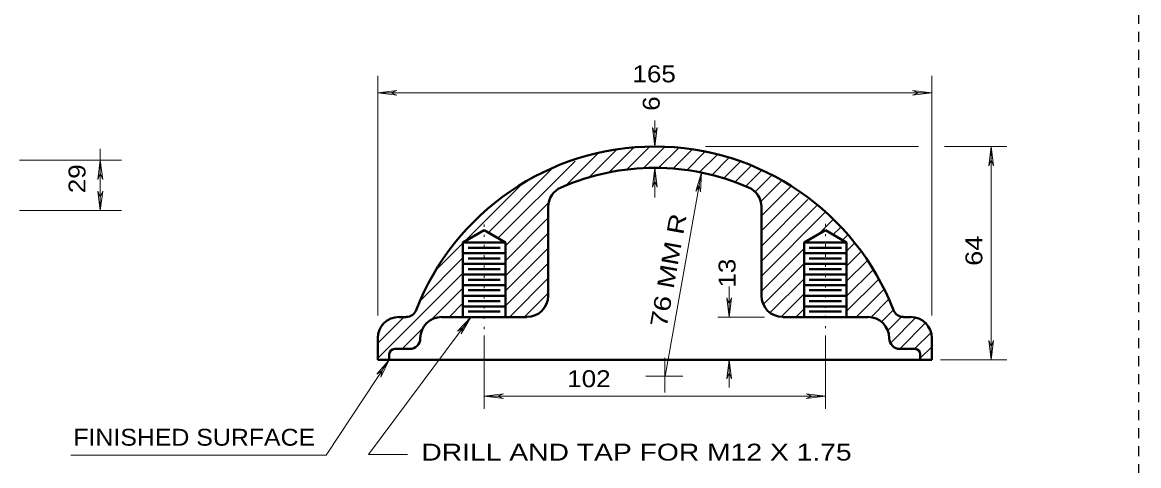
# Model space of a CAD drawing. Extents: x 312583 to 312853, y 144419 to 144586.
# Drawn here: x 312718.5 to 312768.6, y 144534.6 to 144554.6 of the extents above; entities that cross this region are included whole.
import ezdxf

# ---------------------------------------------------------------- set-up
doc = ezdxf.new("R2010")
doc.units = 0
doc.header["$LTSCALE"] = 0.3
doc.linetypes.add('DOTTED', pattern=[1.5, 0.3, -1.2])
doc.linetypes.add('SHORT_DASHED', pattern=[2.7, 1.5, -1.2])
doc.layers.add('1', color=7, linetype='Continuous', lineweight=13)

msp = doc.modelspace()

# ---------------------------------------------------------------- linework, layer by layer
at = {"layer": '1', "linetype": 'SHORT_DASHED', "lineweight": 25}
msp.add_line((312768.638, 144508.3213), (312768.638, 144560.0713), dxfattribs=at)
at = {"layer": '1'}
for p, q in [((312734.4268, 144541.3737), (312734.4268, 144552.1607)), ((312759.3435, 144541.3737), (312759.3435, 144552.1607)), ((312734.4268, 144551.3941), (312735.2931, 144551.5014)), ((312735.2931, 144551.5014), (312735.0171, 144551.3941)), ((312758.4771, 144551.5014), (312758.7531, 144551.3941)), ((312759.3435, 144551.3941), (312758.4771, 144551.5014)), ((312734.4268, 144551.3941), (312759.3435, 144551.3941)), ((312734.4268, 144551.3941), (312735.2931, 144551.2867)), ((312735.2931, 144551.2867), (312735.0171, 144551.3941)), ((312758.4771, 144551.2867), (312758.7531, 144551.3941)), ((312759.3435, 144551.3941), (312758.4771, 144551.2867)), ((312746.8851, 144548.9714), (312746.8851, 144550.1444)), ((312746.7778, 144549.8377), (312746.8851, 144549.5617)), ((312746.8851, 144548.9714), (312746.7778, 144549.8377)), ((312746.9925, 144549.8377), (312746.8851, 144549.5617)), ((312746.8851, 144548.9714), (312746.9925, 144549.8377)), ((312745.6278, 144547.9364), (312746.6475, 144548.9637)), ((312749.1698, 144548.9714), (312758.7455, 144548.9714)), ((312759.9031, 144548.9714), (312762.7168, 144548.9714)), ((312762.0115, 144548.9714), (312761.9041, 144548.1051)), ((312762.0115, 144539.3881), (312762.0115, 144548.9714)), ((312762.0115, 144548.9714), (312762.1188, 144548.1051)), ((312721.9556, 144546.1026), (312721.9556, 144548.8703)), ((312742.8525, 144547.2004), (312744.3168, 144548.6647)), ((312743.8798, 144547.5454), (312745.1755, 144548.8411)), ((312744.8228, 144547.8137), (312745.9115, 144548.9024)), ((312746.3715, 144548.0054), (312747.3068, 144548.9407)), ((312747.0538, 144548.0131), (312747.9278, 144548.8871)), ((312747.7055, 144547.9824), (312748.5565, 144548.8334)), ((312748.3188, 144547.9211), (312749.1315, 144548.7337)), ((312748.8938, 144547.8214), (312749.6681, 144548.5957)), ((312718.3216, 144548.3643), (312722.9063, 144548.3643)), ((312721.9556, 144548.3643), (312721.8483, 144547.4979)), ((312721.9556, 144548.3643), (312722.063, 144547.4979)), ((312739.4025, 144545.1074), (312742.2775, 144547.9824)), ((312739.8395, 144544.8621), (312743.2971, 144548.3197)), ((312746.8851, 144548.0131), (312746.7778, 144547.1467)), ((312746.8851, 144546.6791), (312746.8851, 144548.0131)), ((312746.8851, 144548.0131), (312746.9925, 144547.1467)), ((312749.4458, 144547.6911), (312750.2048, 144548.4501)), ((312749.9595, 144547.5301), (312750.7338, 144548.3044)), ((312750.4655, 144547.3537), (312751.2168, 144548.1127)), ((312761.9041, 144548.1051), (312762.0115, 144548.3811)), ((312762.1188, 144548.1051), (312762.0115, 144548.3811)), ((312721.8483, 144547.4979), (312721.9556, 144547.7739)), ((312722.063, 144547.4979), (312721.9556, 144547.7739)), ((312747.3451, 144538.6444), (312748.9781, 144547.8061)), ((312748.9781, 144547.8061), (312748.7251, 144546.9704)), ((312748.9781, 144547.8061), (312748.9321, 144546.9321)), ((312750.9638, 144547.1774), (312751.6691, 144547.8827)), ((312751.3778, 144546.9167), (312752.1138, 144547.6527)), ((312721.8483, 144546.9689), (312721.9556, 144546.6929)), ((312721.9556, 144546.1026), (312721.8483, 144546.9689)), ((312722.063, 144546.9689), (312721.9556, 144546.6929)), ((312721.9556, 144546.1026), (312722.063, 144546.9689)), ((312738.3138, 144544.6934), (312740.9205, 144547.3001)), ((312746.7778, 144547.1467), (312746.8851, 144547.4227)), ((312746.9925, 144547.1467), (312746.8851, 144547.4227)), ((312748.7251, 144546.9704), (312748.8785, 144547.2234)), ((312748.9321, 144546.9321), (312748.8785, 144547.2234)), ((312751.6461, 144546.5027), (312752.5661, 144547.4227)), ((312751.6768, 144545.8587), (312752.9878, 144547.1697)), ((312740.1845, 144544.5247), (312742.1778, 144546.5257)), ((312751.6768, 144545.1841), (312753.3788, 144546.8861)), ((312751.6768, 144544.5017), (312753.7698, 144546.5947)), ((312718.3216, 144546.1026), (312722.9063, 144546.1026)), ((312751.6768, 144543.8271), (312754.1685, 144546.3187)), ((312751.6768, 144543.1524), (312754.5595, 144546.0351)), ((312740.1845, 144543.8501), (312742.0935, 144545.7667)), ((312754.2375, 144545.0307), (312754.8891, 144545.6824)), ((312740.1845, 144543.1754), (312742.0935, 144545.0844)), ((312754.8968, 144545.0154), (312755.2111, 144545.3221)), ((312755.3261, 144544.7624), (312755.5255, 144544.9694)), ((312737.0795, 144543.4591), (312738.2678, 144544.6474)), ((312755.5101, 144544.2717), (312755.8475, 144544.6091)), ((312736.3818, 144542.0791), (312738.2601, 144543.9651)), ((312740.1845, 144542.4931), (312742.0935, 144544.4097)), ((312751.6768, 144542.4701), (312753.5935, 144544.3867)), ((312755.5101, 144543.5971), (312756.1695, 144544.2487)), ((312740.1845, 144541.8184), (312742.0935, 144543.7274)), ((312751.7995, 144541.9104), (312753.5935, 144543.7121)), ((312755.5101, 144542.9147), (312756.4301, 144543.8347)), ((312734.4268, 144539.4494), (312738.2601, 144543.2827)), ((312740.3455, 144541.3047), (312742.0935, 144543.0527)), ((312752.0908, 144541.5271), (312753.5935, 144543.0297)), ((312755.5101, 144542.2401), (312756.6908, 144543.4131)), ((312755.5101, 144541.5654), (312756.9438, 144542.9914)), ((312736.8571, 144541.2051), (312738.2601, 144542.6081)), ((312750.2278, 144541.3047), (312750.2278, 144542.6847)), ((312755.9318, 144541.3047), (312757.1891, 144542.5621)), ((312737.6391, 144541.3047), (312738.2601, 144541.9334)), ((312741.0278, 144541.3124), (312742.0935, 144542.3781)), ((312750.1205, 144542.1711), (312750.2278, 144541.8951)), ((312750.2278, 144541.3047), (312750.1205, 144542.1711)), ((312750.3351, 144542.1711), (312750.2278, 144541.8951)), ((312750.2278, 144541.3047), (312750.3351, 144542.1711)), ((312752.5738, 144541.3277), (312753.5935, 144542.3551)), ((312756.5835, 144541.2741), (312757.4115, 144542.1097)), ((312753.2255, 144541.3047), (312753.5935, 144541.6727)), ((312757.0435, 144541.0594), (312757.6108, 144541.6267)), ((312734.0128, 144535.1177), (312738.6205, 144541.3047)), ((312734.4268, 144540.1317), (312735.5845, 144541.2894)), ((312738.6205, 144541.3047), (312738.0148, 144540.6761)), ((312738.6205, 144541.3047), (312738.1835, 144540.5457)), ((312751.8225, 144541.3047), (312749.7141, 144541.3047)), ((312757.3425, 144540.6837), (312757.9865, 144541.3277)), ((312757.5188, 144540.1777), (312758.6075, 144541.2664)), ((312757.8945, 144539.8787), (312759.0751, 144541.0594)), ((312735.5231, 144539.8711), (312736.5351, 144540.8831)), ((312738.0148, 144540.6761), (312738.2678, 144540.8294)), ((312738.1835, 144540.5457), (312738.2678, 144540.8294)), ((312739.2185, 144540.4691), (312739.2185, 144537.1724)), ((312754.5518, 144540.4691), (312754.5518, 144537.1724)), ((312758.5615, 144539.8711), (312759.3128, 144540.6147)), ((312758.8221, 144539.4494), (312759.3435, 144539.9707)), ((312761.9041, 144540.2544), (312762.0115, 144539.9784)), ((312762.0115, 144539.3881), (312761.9041, 144540.2544)), ((312762.1188, 144540.2544), (312762.0115, 144539.9784)), ((312762.0115, 144539.3881), (312762.1188, 144540.2544)), ((312747.3375, 144537.9084), (312747.3375, 144539.4724)), ((312734.9481, 144539.3881), (312732.1109, 144535.0937)), ((312734.9481, 144539.3881), (312734.3808, 144538.7287)), ((312734.9481, 144539.3881), (312734.5648, 144538.6061)), ((312750.2278, 144539.3881), (312750.1205, 144538.5217)), ((312750.2278, 144539.3881), (312750.3351, 144538.5217)), ((312750.2278, 144538.1307), (312750.2278, 144539.3881)), ((312759.7345, 144539.3881), (312762.7168, 144539.3881)), ((312734.3808, 144538.7287), (312734.6261, 144538.8974)), ((312734.5648, 144538.6061), (312734.6261, 144538.8974)), ((312746.4788, 144538.6444), (312748.1425, 144538.6444)), ((312750.1205, 144538.5217), (312750.2278, 144538.7977)), ((312750.3351, 144538.5217), (312750.2278, 144538.7977)), ((312739.2185, 144537.7474), (312740.0848, 144537.8547)), ((312739.2185, 144537.7474), (312754.5518, 144537.7474)), ((312739.2185, 144537.7474), (312740.0848, 144537.6401)), ((312740.0848, 144537.8547), (312739.8088, 144537.7474)), ((312740.0848, 144537.6401), (312739.8088, 144537.7474)), ((312753.6855, 144537.8547), (312753.9615, 144537.7474)), ((312754.5518, 144537.7474), (312753.6855, 144537.8547)), ((312753.6855, 144537.6401), (312753.9615, 144537.7474)), ((312754.5518, 144537.7474), (312753.6855, 144537.6401)), ((312732.1109, 144535.0937), (312720.6336, 144535.0937)), ((312735.7608, 144535.1177), (312734.0128, 144535.1177))]:
    msp.add_line(p, q, dxfattribs=at)
at = {"layer": '1', "lineweight": 40}
for p, q in [((312742.0935, 144546.2574), (312742.0935, 144542.2631)), ((312751.6768, 144546.2574), (312751.6768, 144542.2631)), ((312738.2601, 144544.6627), (312739.2185, 144545.2147)), ((312740.1768, 144544.6627), (312739.2185, 144545.2147)), ((312753.5935, 144544.6627), (312754.5518, 144545.2147)), ((312755.5101, 144544.6627), (312754.5518, 144545.2147)), ((312738.2601, 144544.6627), (312738.2601, 144541.3047)), ((312738.2601, 144544.6627), (312740.1768, 144544.6627)), ((312740.1768, 144544.6627), (312740.1768, 144541.3047)), ((312753.5935, 144544.6627), (312753.5935, 144541.3047)), ((312753.5935, 144544.6627), (312755.5101, 144544.6627)), ((312755.5101, 144544.6627), (312755.5101, 144541.3047)), ((312738.2601, 144544.1797), (312740.1768, 144544.1797)), ((312738.4978, 144544.4251), (312739.9391, 144544.4251)), ((312738.4978, 144543.9421), (312739.9391, 144543.9421)), ((312753.5935, 144544.1797), (312755.5101, 144544.1797)), ((312753.8311, 144544.4251), (312755.2725, 144544.4251)), ((312753.8311, 144543.9421), (312755.2725, 144543.9421)), ((312738.2601, 144543.7044), (312740.1768, 144543.7044)), ((312738.4978, 144543.4667), (312739.9391, 144543.4667)), ((312753.5935, 144543.7044), (312755.5101, 144543.7044)), ((312753.8311, 144543.4667), (312755.2725, 144543.4667)), ((312738.2601, 144543.2214), (312740.1768, 144543.2214)), ((312738.4978, 144542.9837), (312739.9391, 144542.9837)), ((312753.5935, 144543.2214), (312755.5101, 144543.2214)), ((312753.8311, 144542.9837), (312755.2725, 144542.9837)), ((312738.2601, 144542.7461), (312740.1768, 144542.7461)), ((312738.4978, 144542.5084), (312739.9391, 144542.5084)), ((312753.5935, 144542.7461), (312755.5101, 144542.7461)), ((312753.8311, 144542.5084), (312755.2725, 144542.5084)), ((312738.2601, 144542.2631), (312740.1768, 144542.2631)), ((312738.4978, 144542.0254), (312739.9391, 144542.0254)), ((312753.5935, 144542.2631), (312755.5101, 144542.2631)), ((312753.8311, 144542.0254), (312755.2725, 144542.0254)), ((312738.2601, 144541.7877), (312740.1768, 144541.7877)), ((312738.4978, 144541.5501), (312739.9391, 144541.5501)), ((312753.5935, 144541.7877), (312755.5101, 144541.7877)), ((312753.8311, 144541.5501), (312755.2725, 144541.5501)), ((312735.3851, 144541.3047), (312735.7148, 144541.3047)), ((312737.3018, 144541.3047), (312741.1351, 144541.3047)), ((312752.6351, 144541.3047), (312756.4685, 144541.3047)), ((312758.0631, 144541.3047), (312758.3851, 144541.3047)), ((312734.4268, 144540.3464), (312734.4268, 144539.3881)), ((312759.3435, 144540.3464), (312759.3435, 144539.3881)), ((312734.9481, 144539.6334), (312734.9481, 144539.3881)), ((312735.1935, 144539.8711), (312735.8681, 144539.8711)), ((312758.5845, 144539.8711), (312757.9098, 144539.8711)), ((312758.8221, 144539.6334), (312758.8221, 144539.3881)), ((312734.4268, 144539.3881), (312759.3435, 144539.3881))]:
    msp.add_line(p, q, dxfattribs=at)
at = {"layer": '1', "linetype": 'DOTTED'}
for p, q in [((312739.2185, 144545.4677), (312739.2185, 144540.4691)), ((312754.5518, 144545.4984), (312754.5518, 144540.4691))]:
    msp.add_line(p, q, dxfattribs=at)
at = {"layer": '1', "lineweight": 40}
for centre, radius, start, end in [((312746.8851, 144537.4752), 11.5, 21.1002, 158.90079), ((312746.8851, 144537.4752), 10.5417, 66.41835, 113.58165), ((312743.0518, 144546.2585), 0.9583, 113.57818, 180), ((312750.7185, 144546.2585), 0.9583, 0, 66.42182), ((312741.1351, 144542.2669), 0.9583, 270, 0), ((312752.6351, 144542.2669), 0.9583, 180, 270), ((312735.7091, 144541.7877), 0.4792, 270, 338.8998), ((312758.0611, 144541.7877), 0.4792, 201.1002, 270), ((312735.3851, 144540.3502), 0.9583, 90, 180), ((312737.3018, 144540.3502), 0.9583, 90, 180), ((312756.4685, 144540.3502), 0.9583, 0, 90), ((312758.3851, 144540.3502), 0.9583, 0, 90), ((312735.8643, 144540.3502), 0.4792, 270, 0), ((312757.906, 144540.3502), 0.4792, 180, 270), ((312735.1877, 144539.6315), 0.2396, 90, 180), ((312758.5825, 144539.6315), 0.2396, 0, 90)]:
    msp.add_arc(centre, radius, start, end, dxfattribs=at)

# ---------------------------------------------------------------- texts
at = {"layer": '1'}
for s, width, p in [('165 ', 1.15, (312745.8798, 144551.8659)), ('102 ', 1.15, (312742.948, 144538.1514)), ('FINISHED SURFACE', 1.1, (312720.7438, 144535.5182)), ('DRILL AND TAP FOR M12 X 1.75 ', 1.25, (312736.3895, 144534.8484))]:
    msp.add_text(s, height=0.76, dxfattribs=dict(at, width=width)).set_placement(p)
for s, rotation, width, p in [('6 ', 90, 1.15, (312747.1037, 144550.5848)), ('29 ', 90, 1.15, (312721.29, 144546.8771)), ('76 MM R', 79.87, 1.25, (312747.4149, 144540.807)), ('64 ', 90, 1.2, (312761.6109, 144543.6116)), (' 13 ', 90, 1.15, (312750.5127, 144542.3049))]:
    msp.add_text(s, height=0.76, rotation=rotation, dxfattribs=dict(at, width=width)).set_placement(p)

doc.saveas('drawing.dxf')
